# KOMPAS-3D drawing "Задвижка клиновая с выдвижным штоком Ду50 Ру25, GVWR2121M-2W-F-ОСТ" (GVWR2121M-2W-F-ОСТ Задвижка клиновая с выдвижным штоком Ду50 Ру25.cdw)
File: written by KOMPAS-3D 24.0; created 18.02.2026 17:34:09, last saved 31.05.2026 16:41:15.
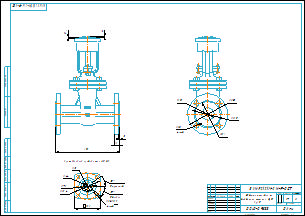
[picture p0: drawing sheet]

Document properties: Автор: R2D2; Форматы листов документа: A2; Полное имя файла: GVWR2121M-2W-F-ОСТ Задвижка клиновая с выдвижным штоком Ду50 Ру25.m3d; Масса: 17; Наименование: Задвижка клиновая с выдвижным штоком Ду50 Ру25; Количество листов документа: 1; Примечание: D040-09833

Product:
- Part/product: Задвижка клиновая с выдвижным штоком Ду50 Ру25  | designation GVWR2121M-2W-F-ОСТ
    Масса: 17
    Раздел спецификации: Прочие изделия
    Примечание: D040-09833

Views: Проекционный вид 3
Referenced files in E:\Работа\Зайцев\Для компаса\: чертеж DN.ru А3.cdt
Referenced files in E:\Работа\Зайцев\GVWR2121M-2W-F-ОСТ Задвижка клиновая 30с964нж DN.ru Ду50-300 Ру25\исходные материалы\DN50\DN50\: GVWR2121M-2W-F-ОСТ Задвижка клиновая с выдвижным штоком Ду50 Ру25.m3d
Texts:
  Присоединение привода тип АК (А)
  чертеж DN.ru А3.cdt
  Задвижка клиновая с
  выдвижным штоком Ду50
  Ру25
  GVWR2121M-2W-F-ОСТ
  Задвижка клиновая с выдвижным штоком Ду50 Ру25
  GVWR2121M-2W-F-ОСТ Задвижка клиновая с выдвижным штоком Ду50 Ру25
Dimensions and other numbers on the sheet: 100; 5 кулачков; 5 впадин; 14(М12); 4 отв.; 104; 70; 44; 32; 1:2; 0; 1; 2; 17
